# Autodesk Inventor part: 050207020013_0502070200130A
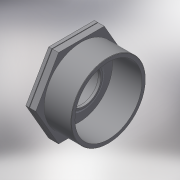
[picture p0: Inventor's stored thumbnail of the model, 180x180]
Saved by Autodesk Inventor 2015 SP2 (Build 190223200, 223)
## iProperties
Created: 2017-05
Part Number: 050207020013_0502070200130A
Material: Generic
Description: PLASSON REDUCING BUSHING 2"-1.1/4"
Document SubType Name: Modeling
Designer: KIM
Density: 1 g/cm^3
Appearance: Default
Author: KIM
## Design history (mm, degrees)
derived "050207.ipt"
feature "Solid1::050207.ipt"
tag "TaggingFeature1"
body "Solid1"
other parameters: "d1" = 59.614, "d2" = 63, "d5" = 26, "d8" = 0.41, "d12" = 0, "d15" = 41, "d19" = 0, "d30" = 9.11111, "d31" = 4.55556, "d33" = 38.952, "d34" = 53.6526, "d36" = 3.15, "d37" = 46.7424, "d38" = 27.06, "d39" = 35.0568, "d40" = 2.6, "d41" = 0, "H_" = 41, "R_" = 59.614, "E_" = 63, "l_2" = 26, "Rp_" = 38.952
